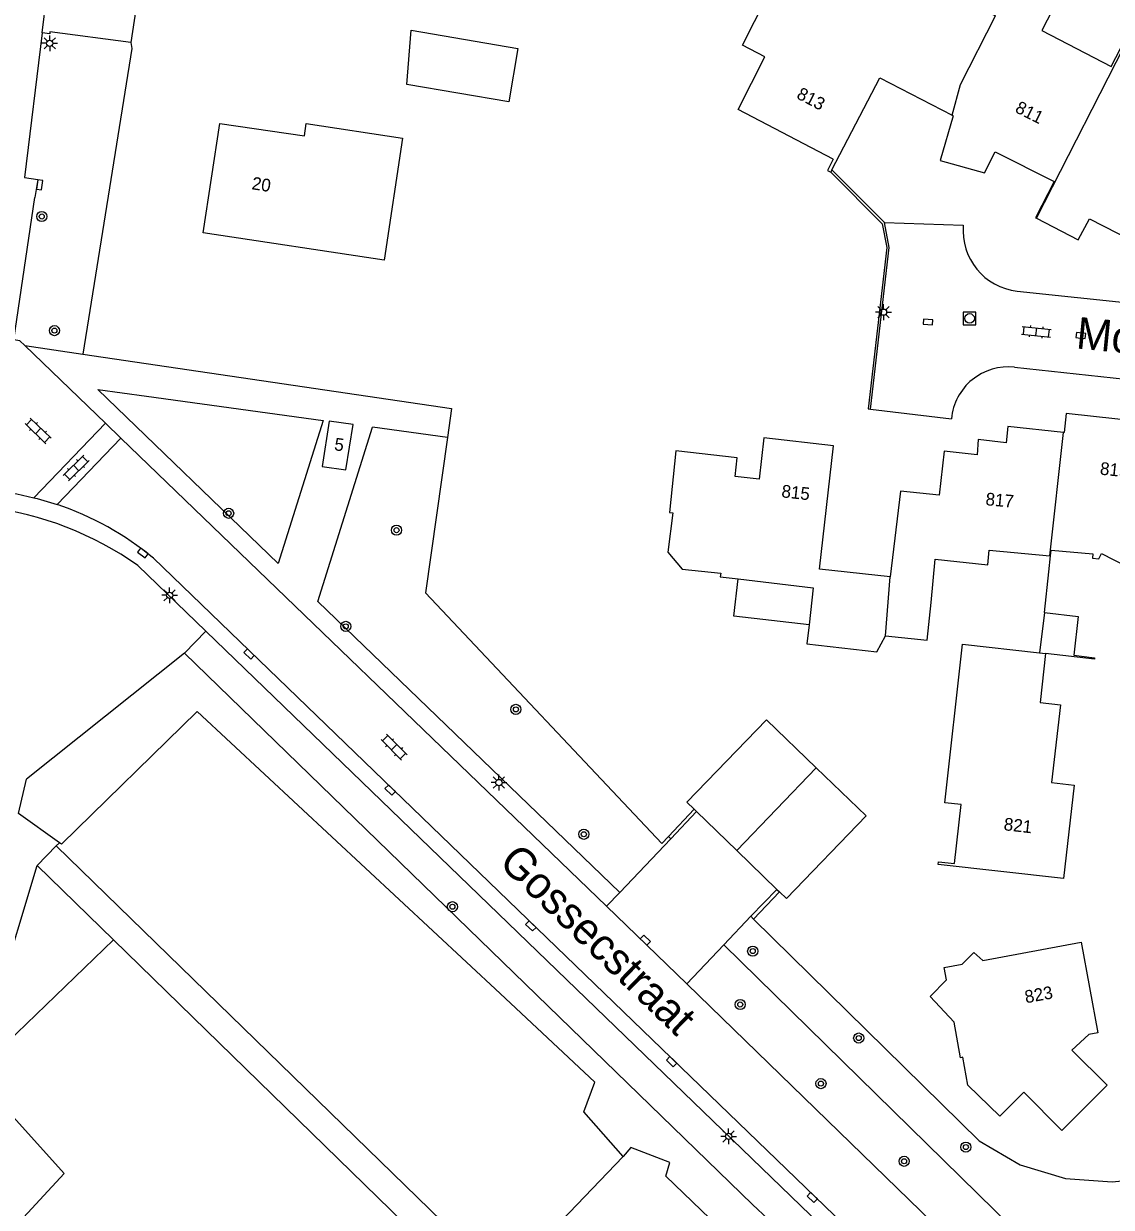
# Model space of a CAD drawing. Extents: x 132999 to 136000, y 398499 to 400501.
# Drawn here: x 133253.2 to 133339.2, y 399007.4 to 399100.9 of the extents above; entities that cross this region are included whole.
import ezdxf

# ---------------------------------------------------------------- set-up
doc = ezdxf.new("R2010")
doc.units = 0
for name, color, linetype in [('gg-afsc-erfafscheiding', 7, 'Continuous'), ('gg-afsc-hekwerk', 7, 'Continuous'), ('gg-afsc-muur', 7, 'Continuous'), ('gg-anno-huisnummerreeks BGT', 7, 'Continuous'), ('gg-anno-openbare ruimte label', 7, 'Continuous'), ('gg-bbg-bijgebouw', 7, 'Continuous'), ('gg-bbg-gedigitaliseerde bebouwing', 7, 'Continuous'), ('gg-bbg-gedigitaliseerde bijgebouw', 7, 'Continuous'), ('gg-bbg-hoofdgebouw', 7, 'Continuous'), ('gg-bbg-luifel en loopbrug', 7, 'Continuous'), ('gg-bbg-tussenscheiding', 7, 'Continuous'), ('gg-knt-verharding', 7, 'Continuous'), ('gg-knt-verharding nz', 7, 'Continuous'), ('gt-grn-groengrens', 7, 'Continuous'), ('gt-grn-vlakafsluiter', 7, 'Continuous'), ('gt-symb-boom', 7, 'Continuous'), ('gt-symb-klinker verharding', 7, 'Continuous'), ('gt-symb-kolk', 7, 'Continuous'), ('gt-symb-lichtmast', 7, 'Continuous'), ('gt-symb-rioolschacht', 7, 'Continuous')]:
    doc.layers.add(name, color=color, linetype=linetype)

# ---------------------------------------------------------------- blocks, each defined once
blk = doc.blocks.new('gt0-KOLK')
at = {"layer": 'gt-symb-kolk'}
blk.add_lwpolyline([(0, 0), (0.375, 0), (0.375, 0.4), (-0.375, 0.4), (-0.375, 0), (0, 0)], dxfattribs=at)
blk = doc.blocks.new('gt0-KL1')
at = {"layer": 'gt-symb-klinker verharding'}
for p, q in [((-1.15, 0.3), (1.15, 0.3)), ((-1, -0.3), (-1, 0.3)), ((-0.5, 0.3), (-0.5, 0.45)), ((0, -0.3), (0, 0.3)), ((0.5, 0.3), (0.5, 0.45)), ((1, -0.3), (1, 0.3)), ((-1.15, -0.3), (1.15, -0.3)), ((-0.5, -0.45), (-0.5, -0.3)), ((0.5, -0.45), (0.5, -0.3))]:
    blk.add_line(p, q, dxfattribs=at)
blk = doc.blocks.new('gt0-RS')
at = {"layer": 'gt-symb-rioolschacht'}
blk.add_lwpolyline([(-0.5, -0.5), (0.5, -0.5), (0.5, 0.5), (-0.5, 0.5)], close=True, dxfattribs=at)
blk.add_circle((0, 0), 0.375, dxfattribs=at)
blk = doc.blocks.new('gt0-LMAST')
at = {"layer": 'gt-symb-lichtmast'}
for p, q in [((-0.182, 0.173), (-0.447, 0.438)), ((-0.005, 0.246), (-0.005, 0.621)), ((0.172, 0.173), (0.437, 0.438)), ((-0.255, -0.004), (-0.63, -0.004)), ((-0.182, -0.181), (-0.447, -0.446)), ((-0.005, -0.254), (-0.005, -0.629)), ((0.437, -0.446), (0.172, -0.181)), ((0.245, -0.004), (0.62, -0.004))]:
    blk.add_line(p, q, dxfattribs=at)
blk.add_circle((-0.005, -0.004), 0.25, dxfattribs=at)
blk = doc.blocks.new('gt0-BOOM')
at = {"layer": 'gt-symb-boom'}
for radius in [0.4, 0.2]:
    blk.add_circle((0, 0), radius, dxfattribs=at)

msp = doc.modelspace()

# ---------------------------------------------------------------- linework, layer by layer
at = {"layer": 'gg-afsc-erfafscheiding'}
for p, q in [((133333.91, 399054.37), (133334.243, 399057.579)), ((133265.94, 399051.145), (133253.46, 399041.187)), ((133265.94, 399051.145), (133310.836, 399007.613)), ((133252.836, 399038.493), (133253.46, 399041.187))]:
    msp.add_line(p, q, dxfattribs=at)
msp.add_lwpolyline([(133310.921, 399030.136), (133328.735, 399012.632), (133331.992, 399010.732), (133335.576, 399009.647), (133339.267, 399009.4), (133343.903, 399009.865)], dxfattribs=at)
at = {"layer": 'gg-afsc-hekwerk'}
msp.add_line((133310.836, 399007.613), (133319.006, 399000), dxfattribs=at)
at = {"layer": 'gg-afsc-muur'}
for p, q in [((133261.788, 399098.912), (133257.904, 399074.766)), ((133321.26, 399085.16), (133317.112, 399089.327)), ((133334.243, 399057.579), (133334.382, 399058.841)), ((133304.194, 399036.678), (133306.213, 399038.828)), ((133306.414, 399038.633), (133304.376, 399036.489)), ((133304.376, 399036.489), (133304.194, 399036.678)), ((133312.763, 399032.493), (133310.712, 399030.372)), ((133310.921, 399030.136), (133312.97, 399032.293)), ((133310.712, 399030.372), (133310.921, 399030.136))]:
    msp.add_line(p, q, dxfattribs=at)
for points in [[(133317.02, 399089.15), (133321.076, 399085.062), (133321.438, 399083.185), (133319.961, 399070.443), (133320.16, 399070.42)], [(133320.16, 399070.42), (133321.64, 399083.19), (133321.26, 399085.16)], [(133257.904, 399074.766), (133287.054, 399070.481), (133286.726, 399068.172)], [(133286.726, 399068.172), (133284.982, 399055.9), (133303.656, 399036.105), (133304.194, 399036.678)]]:
    msp.add_lwpolyline(points, dxfattribs=at)
at = {"layer": 'gg-bbg-bijgebouw'}
for p, q in [((133333.91, 399054.37), (133333.515, 399051.186)), ((133306.213, 399038.828), (133306.414, 399038.633)), ((133306.414, 399038.633), (133309.594, 399035.558)), ((133309.594, 399035.558), (133312.763, 399032.493)), ((133312.763, 399032.493), (133312.97, 399032.293))]:
    msp.add_line(p, q, dxfattribs=at)
for points in [[(133333.91, 399054.37), (133336.57, 399054.04), (133336.23, 399050.99), (133337.87, 399050.78), (133337.86, 399050.67), (133333.99, 399051.12)], [(133315.867, 399042.103), (133311.948, 399045.889), (133305.647, 399039.375), (133306.213, 399038.828)], [(133312.97, 399032.293), (133313.515, 399031.766), (133319.816, 399038.288), (133315.867, 399042.103)]]:
    msp.add_lwpolyline(points, dxfattribs=at)
at = {"layer": 'gg-bbg-gedigitaliseerde bebouwing'}
msp.add_line((133317.22, 399090.17), (133309.694, 399094.094), dxfattribs=at)
for points in [[(133309.694, 399094.094), (133311.82, 399098.24), (133310.04, 399099.16), (133311.93, 399102.92), (133313.7, 399102), (133315.59, 399105.65), (133323.09, 399101.75), (133324.47, 399104.41), (133330.047, 399101.476)], [(133335.78, 399104.37), (133333.69, 399100.32), (133339.18, 399097.48), (133340.68, 399100.37), (133340.828, 399100.295)]]:
    msp.add_lwpolyline(points, dxfattribs=at)
at = {"layer": 'gg-bbg-gedigitaliseerde bijgebouw'}
msp.add_lwpolyline([(133292.284, 399098.904), (133291.589, 399094.696), (133283.517, 399096.057), (133283.848, 399100.355), (133292.284, 399098.904)], dxfattribs=at)
at = {"layer": 'gg-bbg-hoofdgebouw'}
for p, q in [((133317.112, 399089.327), (133317.02, 399089.15)), ((133334.33, 399058.846), (133334.382, 399058.841))]:
    msp.add_line(p, q, dxfattribs=at)
for points in [[(133317.112, 399089.327), (133320.89, 399096.59), (133326.604, 399093.634)], [(133326.604, 399093.634), (133326.69, 399093.59), (133325.67, 399090.06), (133329.17, 399089.08), (133330.02, 399090.75), (133334.67, 399088.39), (133333.21, 399085.53), (133333.282, 399085.493)], [(133267.429, 399084.335), (133268.747, 399092.988), (133275.421, 399091.994), (133275.568, 399092.981), (133283.169, 399091.832), (133281.722, 399082.189), (133267.429, 399084.335)], [(133317.22, 399090.17), (133316.76, 399089.28), (133317.02, 399089.15)], [(133333.282, 399085.493), (133336.58, 399083.8), (133337.47, 399085.45), (133342.98, 399082.63)], [(133334.382, 399058.841), (133334.424, 399059.289), (133337.72, 399058.98), (133337.69, 399058.66), (133338.19, 399058.61), (133338.41, 399059.02), (133341.33, 399057.52), (133346.53, 399067.68), (133343.55, 399069.21), (133335.63, 399070.07), (133335.46, 399068.58), (133335.423, 399068.584)], [(133277.38, 399069.46), (133276.82, 399065.9), (133278.71, 399065.63), (133279.28, 399069.2), (133277.38, 399069.46)], [(133335.423, 399068.584), (133331.01, 399069.06), (133330.87, 399067.76), (133328.67, 399068.02), (133328.59, 399066.82), (133325.98, 399067.1), (133325.58, 399063.63), (133322.52, 399063.94), (133321.72, 399057.17)], [(133321.72, 399057.17), (133316.12, 399057.78), (133317.23, 399067.53), (133311.72, 399068.15), (133311.35, 399064.88), (133309.47, 399065.09), (133309.63, 399066.58), (133304.77, 399067.13), (133304.27, 399062.25), (133304.54, 399062.22), (133304.13, 399059.13), (133305.28, 399057.79), (133308.32, 399057.46), (133308.29, 399057.18), (133309.693, 399057.016)], [(133321.34, 399052.51), (133324.63, 399052.17), (133324.95, 399055.15), (133325.27, 399058.56), (133329.43, 399058.13), (133329.548, 399059.294), (133334.33, 399058.846)], [(133309.693, 399057.016), (133315.63, 399056.32), (133315.305, 399053.381)], [(133315.305, 399053.381), (133315.14, 399051.89), (133320.67, 399051.25), (133321.34, 399052.51)], [(133333.99, 399051.12), (133333.57, 399047.25), (133335.16, 399047.06), (133334.46, 399040.94), (133336.26, 399040.72), (133335.41, 399033.34), (133325.5, 399034.45), (133325.52, 399034.67), (133326.8, 399034.54), (133327.32, 399039.19), (133326.03, 399039.34), (133327.42, 399051.86), (133333.515, 399051.186)], [(133335.27, 399013.46), (133332.277, 399016.463), (133330.386, 399014.578), (133327.851, 399017.032), (133327.456, 399019.229), (133327.26, 399019.19), (133326.757, 399021.992), (133324.862, 399024.039), (133326.156, 399025.338), (133325.98, 399026.32), (133327.396, 399026.583), (133328.327, 399027.518), (133329.023, 399026.885), (133336.8, 399028.33)], [(133336.8, 399028.33), (133338.12, 399021.17), (133337.41, 399021.04), (133336.06, 399019.8), (133338.86, 399017.02), (133335.27, 399013.46)]]:
    msp.add_lwpolyline(points, dxfattribs=at)
at = {"layer": 'gg-bbg-luifel en loopbrug'}
msp.add_lwpolyline([(133315.305, 399053.381), (133309.352, 399054.07), (133309.693, 399057.016)], dxfattribs=at)
at = {"layer": 'gg-bbg-tussenscheiding'}
for p, q in [((133333.282, 399085.493), (133340.828, 399100.295)), ((133334.33, 399058.846), (133335.423, 399068.584)), ((133321.34, 399052.51), (133321.72, 399057.17)), ((133333.515, 399051.186), (133333.99, 399051.12)), ((133309.594, 399035.558), (133315.867, 399042.103))]:
    msp.add_line(p, q, dxfattribs=at)
msp.add_lwpolyline([(133326.604, 399093.634), (133327.28, 399096.05), (133330.047, 399101.476)], dxfattribs=at)
at = {"layer": 'gg-knt-verharding'}
for p, q in [((133254.711, 399100.145), (133255.356, 399105.605)), ((133262.236, 399102.885), (133261.719, 399099.369)), ((133252.472, 399075.907), (133254.126, 399087.135)), ((133321.26, 399085.16), (133327.49, 399084.95)), ((133331.759, 399079.741), (133355.08, 399077.25)), ((133259.701, 399069.3), (133253.325, 399075.442)), ((133331.53, 399073.73), (133347.531, 399072.03)), ((133320.16, 399070.42), (133326.56, 399069.662)), ((133254.044, 399063.426), (133259.701, 399069.3)), ((133260.925, 399068.121), (133259.701, 399069.3)), ((133260.925, 399068.121), (133255.887, 399062.89)), ((133299.303, 399031.153), (133260.925, 399068.121)), ((133267.626, 399052.892), (133262.257, 399058.073)), ((133324.299, 399000), (133263.489, 399058.659)), ((133322.443, 399000), (133267.626, 399052.892)), ((133304.376, 399036.489), (133300.337, 399032.24)), ((133300.337, 399032.24), (133299.303, 399031.153)), ((133310.712, 399030.372), (133308.559, 399028.107)), ((133308.559, 399028.107), (133305.647, 399025.043)), ((133333.881, 398997.639), (133305.647, 399025.043))]:
    msp.add_line(p, q, dxfattribs=at)
for points in [[(133254.711, 399100.145), (133253.313, 399088.72), (133254.365, 399088.56), (133254.126, 399087.135)], [(133261.719, 399099.369), (133255.316, 399100.223), (133255.307, 399100.06), (133254.711, 399100.145)], [(133253.325, 399075.442), (133252.931, 399075.822), (133252.472, 399075.907)], [(133250.608, 399064.04), (133252.706, 399063.731), (133254.044, 399063.426)], [(133254.044, 399063.426), (133254.311, 399063.365), (133255.887, 399062.89)]]:
    msp.add_lwpolyline(points, dxfattribs=at)
for centre, radius, start, end in [((133332.282, 399084.524), 4.811, 174.91415, 263.75805), ((133331.038, 399069.261), 4.496, 83.71502, 174.88639), ((133247.129, 399036.611), 26.258, 54.82017, 82.88708), ((133248.143, 399040.031), 24.135, 50.51748, 71.28504)]:
    msp.add_arc(centre, radius, start, end, dxfattribs=at)
at = {"layer": 'gg-knt-verharding nz'}
msp.add_line((133305.647, 399025.043), (133299.303, 399031.153), dxfattribs=at)
at = {"layer": 'gt-grn-groengrens'}
for p, q in [((133253.325, 399075.442), (133257.904, 399074.766)), ((133262.947, 399071.435), (133276.912, 399069.519)), ((133286.726, 399068.172), (133280.817, 399068.988)), ((133265.94, 399051.145), (133267.626, 399052.892)), ((133256.062, 399036.178), (133252.836, 399038.493)), ((133255.811, 399035.921), (133254.316, 399034.387)), ((133256.062, 399036.178), (133255.811, 399035.921)), ((133249.329, 399017.914), (133254.316, 399034.387)), ((133254.316, 399034.387), (133260.346, 399028.509)), ((133260.346, 399028.509), (133249.329, 399017.914))]:
    msp.add_line(p, q, dxfattribs=at)
for points in [[(133276.912, 399069.519), (133273.354, 399058.231), (133259.099, 399071.963), (133262.947, 399071.435)], [(133300.337, 399032.24), (133276.478, 399055.222), (133280.817, 399068.988)], [(133266.948, 399046.55), (133256.231, 399036.057), (133256.062, 399036.178)], [(133300.623, 399011.404), (133297.507, 399014.925), (133298.379, 399017.256), (133290.891, 399024.274), (133266.948, 399046.55)], [(133255.811, 399035.921), (133290.25, 399002.411), (133292.082, 399002.499), (133300.623, 399011.404)], [(133248.081, 398956.982), (133249.673, 398958.97), (133266.464, 398976.331), (133266.183, 398977.707), (133253.481, 398990.349), (133255.067, 398991.826), (133267.737, 398978.846), (133269.143, 398978.846), (133288.746, 398998.823), (133288.52, 399001.057), (133260.346, 399028.509)], [(133308.559, 399028.107), (133340.652, 398996.676), (133344.842, 398999.189), (133343.903, 399009.865)], [(133245.47, 398998.379), (133246.973, 398999.743), (133247.106, 399000), (133256.433, 399010.047), (133249.329, 399017.914)], [(133324.203, 398990.374), (133303.983, 399009.85), (133304.3, 399010.912), (133301.209, 399012.117), (133300.623, 399011.404)]]:
    msp.add_lwpolyline(points, dxfattribs=at)
at = {"layer": 'gt-grn-vlakafsluiter'}
msp.add_line((133261.719, 399099.369), (133261.788, 399098.912), dxfattribs=at)

# ---------------------------------------------------------------- block references
at = {"layer": 'gt-symb-boom'}
for p in [(133254.666, 399085.635), (133255.667, 399076.62), (133269.438, 399062.192), (133282.704, 399060.862), (133278.69, 399053.266), (133292.137, 399046.711), (133287.117, 399031.126), (133310.851, 399027.617), (133309.867, 399023.399), (133319.224, 399020.752), (133316.242, 399017.151), (133327.695, 399012.138), (133322.812, 399011.014)]:
    msp.add_blockref('gt0-BOOM', p, dxfattribs=at)
at = {"layer": 'gt-symb-boom', "rotation": -43.94658952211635}
msp.add_blockref('gt0-BOOM', (133297.505, 399036.843), dxfattribs=at)
at = {"layer": 'gt-symb-klinker verharding'}
for p, rotation in [((133333.267, 399076.53), -6.087008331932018), ((133254.381, 399068.699), 136.05341047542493), ((133257.379, 399065.774), 44.756879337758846), ((133282.506, 399043.72), 135.00000000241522)]:
    msp.add_blockref('gt0-KL1', p, dxfattribs=dict(at, rotation=rotation))
at = {"layer": 'gt-symb-kolk'}
for p, rotation in [((133254.302, 399088.173), -99.264523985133), ((133324.718, 399077.5), 175.1221191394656), ((133336.758, 399076.03), -6.087008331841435), ((133262.783, 399059.219), 143.78311535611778), ((133271.191, 399051.229), 136.05341047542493), ((133282.339, 399040.475), 136.0534104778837), ((133293.455, 399029.753), 136.05341047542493), ((133302.226, 399028.338), -43.94658952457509), ((133304.579, 399019.023), 136.05341047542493), ((133315.694, 399008.3), 136.05341047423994)]:
    msp.add_blockref('gt0-KOLK', p, dxfattribs=dict(at, rotation=rotation))
at = {"layer": 'gt-symb-lichtmast'}
for p in [(133255.304, 399099.321), (133321.19, 399078.084), (133264.775, 399055.72), (133290.799, 399040.931), (133308.949, 399012.985)]:
    msp.add_blockref('gt0-LMAST', p, dxfattribs=at)
at = {"layer": 'gt-symb-rioolschacht'}
msp.add_blockref('gt0-RS', (133327.992, 399077.59), dxfattribs=at)

# ---------------------------------------------------------------- texts
at = {"layer": 'gg-anno-huisnummerreeks BGT'}
for s, rotation, p in [('813', 332.5, (133314.244, 399095.007)), ('811', 333.1, (133331.513, 399093.917)), ('20', 351.3, (133271.216, 399087.793)), ('5', 351.9, (133277.74, 399067.181)), ('819', 353.8, (133338.256, 399065.259)), ('815', 353.6, (133313.088, 399063.467)), ('817', 354.7, (133329.217, 399062.84)), ('821', 353.5, (133330.652, 399037.171)), ('823', 10.4, (133332.44, 399023.49))]:
    msp.add_text(s, height=1, rotation=rotation, dxfattribs=at).set_placement(p)
at = {"layer": 'gg-anno-openbare ruimte label'}
for s, rotation, p in [('Mozartlaan', 354.3, (133336.345, 399075.224)), ('Gossecstraat', 316, (133290.69, 399034.502))]:
    msp.add_text(s, height=2.5, rotation=rotation, dxfattribs=at).set_placement(p)

doc.saveas('drawing.dxf')
